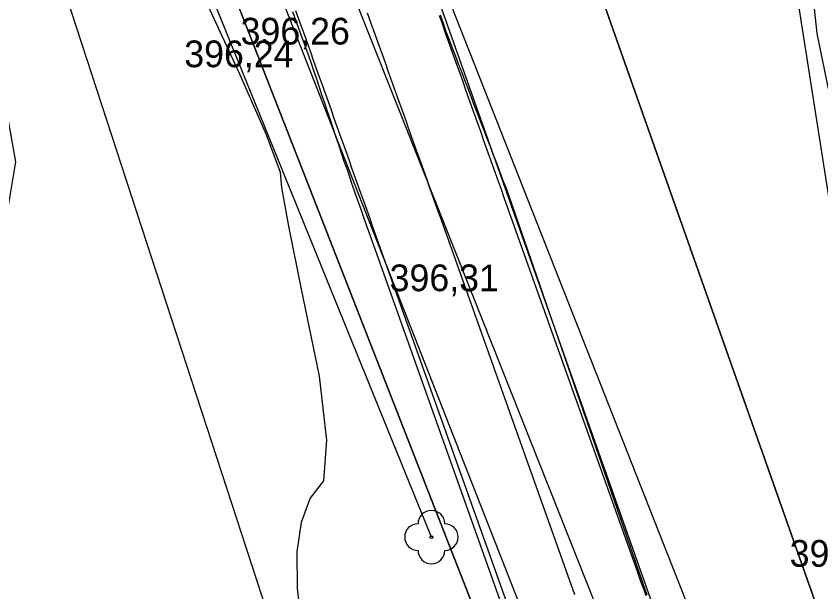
# Model space of a CAD drawing. Extents: x -574342 to -508101, y -1143544 to -1123894.
# Drawn here: x -508450.68 to -508420.54, y -1143237.66 to -1143216.1 of the extents above; entities that cross this region are included whole.
import ezdxf

# ---------------------------------------------------------------- set-up
doc = ezdxf.new("R2010")
doc.units = 0
for name, color, linetype in [('01_PARCELY_NAVRH_PC', 7, 'Continuous'), ('01_PARCELY_NAVRH_ŽP', 7, 'Continuous'), ('1000', 7, 'Continuous'), ('21', 7, 'Continuous'), ('37', 7, 'Continuous'), ('42', 7, 'Continuous'), ('54', 7, 'Continuous'), ('55', 7, 'Continuous'), ('Level 255', 7, 'Continuous'), ('VRST VEDL', 7, 'Continuous')]:
    doc.layers.add(name, color=color, linetype=linetype)

msp = doc.modelspace()

# ---------------------------------------------------------------- linework, layer by layer
at = {"layer": '01_PARCELY_NAVRH_PC'}
msp.add_lwpolyline([(-508451.57, -1143168.14), (-508437.66, -1143207.58), (-508425.52, -1143241.92), (-508422.7, -1143249.88), (-508420.08, -1143265.35), (-508416.18, -1143288.91), (-508414.34, -1143296.2), (-508410.3, -1143304.94), (-508406.96, -1143310.33), (-508402.64, -1143313.55), (-508394.5, -1143317.14), (-508397.53, -1143325.93), (-508402.47, -1143323.55), (-508407.39, -1143320.93), (-508414.82, -1143312.69), (-508418.17, -1143303.49), (-508422.28, -1143289.33), (-508426.41, -1143265.09), (-508431, -1143245.85), (-508431.86, -1143242.81), (-508432.73, -1143240.34), (-508445.99, -1143206.42), (-508454.33, -1143183.49)], dxfattribs=at)
at = {"layer": '01_PARCELY_NAVRH_ŽP'}
for points in [[(-508476.398, -1143116.058), (-508474.05, -1143124.14), (-508467.92, -1143139.18), (-508459.97, -1143152.33), (-508456.09, -1143158.71), (-508451.57, -1143168.14), (-508437.66, -1143207.58), (-508425.52, -1143241.92), (-508422.7, -1143249.88), (-508420.04, -1143252.1), (-508417.38, -1143252.95), (-508415.56, -1143252.78), (-508448.24, -1143160.16), (-508453.75, -1143145.01), (-508465.11, -1143123.03), (-508467.879, -1143116.058)], [(-508467.879, -1143116.058), (-508465.11, -1143123.03), (-508453.75, -1143145.01), (-508448.24, -1143160.16), (-508415.56, -1143252.78), (-508437, -1143116.058)]]:
    msp.add_lwpolyline(points, dxfattribs=at)
msp.add_lwpolyline([(-508455.43, -1143236.54), (-508453.14, -1143234.1), (-508452.04, -1143229.57), (-508450.69, -1143221.56), (-508452.8, -1143209.75), (-508452.72, -1143198.2), (-508454.33, -1143183.49), (-508445.99, -1143206.42), (-508432.73, -1143240.34), (-508433.72, -1143240.11), (-508438.05, -1143241.09), (-508444.11, -1143244.2), (-508446.56, -1143243.12), (-508452.58, -1143244.39)], close=True, dxfattribs=at)
at = {"layer": '1000'}
for points in [[(-508440.333, -1143215.926), (-508440.221, -1143216.235), (-508440.109, -1143216.545), (-508439.997, -1143216.855), (-508439.885, -1143217.165), (-508439.847, -1143217.271), (-508439.773, -1143217.474), (-508439.661, -1143217.784), (-508439.552, -1143218.095), (-508439.448, -1143218.407), (-508439.344, -1143218.72), (-508439.24, -1143219.033), (-508439.136, -1143219.345), (-508439.032, -1143219.658), (-508438.927, -1143219.97), (-508438.823, -1143220.282), (-508438.719, -1143220.595), (-508438.614, -1143220.907), (-508438.509, -1143221.219), (-508438.404, -1143221.532), (-508438.29, -1143221.841), (-508438.183, -1143222.152), (-508438.079, -1143222.465), (-508437.976, -1143222.778), (-508437.865, -1143223.088), (-508437.754, -1143223.398), (-508437.642, -1143223.707), (-508437.531, -1143224.017), (-508437.419, -1143224.327), (-508437.307, -1143224.637), (-508432.319, -1143238.675)], [(-508440.217, -1143215.884), (-508440.106, -1143216.195), (-508439.996, -1143216.505), (-508439.885, -1143216.815), (-508439.775, -1143217.125), (-508439.737, -1143217.232), (-508439.664, -1143217.436), (-508439.554, -1143217.746), (-508439.443, -1143218.056), (-508439.333, -1143218.366), (-508439.222, -1143218.676), (-508439.112, -1143218.987), (-508439.001, -1143219.297), (-508438.89, -1143219.607), (-508438.78, -1143219.917), (-508438.669, -1143220.228), (-508438.559, -1143220.538), (-508438.448, -1143220.848), (-508438.338, -1143221.158), (-508438.227, -1143221.469), (-508438.117, -1143221.779), (-508438.006, -1143222.089), (-508437.896, -1143222.399), (-508437.785, -1143222.71), (-508437.675, -1143223.02), (-508437.564, -1143223.33), (-508437.454, -1143223.64), (-508437.343, -1143223.951), (-508437.233, -1143224.261), (-508437.122, -1143224.571), (-508432.123, -1143238.605)], [(-508434.844, -1143216.068), (-508434.733, -1143216.378), (-508434.623, -1143216.688), (-508434.512, -1143216.999), (-508434.401, -1143217.309), (-508434.291, -1143217.619), (-508434.18, -1143217.929), (-508434.07, -1143218.239), (-508433.959, -1143218.55), (-508433.849, -1143218.86), (-508433.738, -1143219.17), (-508433.628, -1143219.48), (-508433.517, -1143219.791), (-508433.407, -1143220.101), (-508433.296, -1143220.411), (-508433.186, -1143220.721), (-508433.075, -1143221.032), (-508432.965, -1143221.342), (-508432.854, -1143221.652), (-508432.744, -1143221.962), (-508432.633, -1143222.273), (-508432.523, -1143222.583), (-508432.412, -1143222.893), (-508427.412, -1143236.927), (-508427.335, -1143237.143), (-508427.258, -1143237.36), (-508427.181, -1143237.576), (-508427.104, -1143237.793)], [(-508434.801, -1143216.053), (-508434.695, -1143216.365), (-508434.587, -1143216.676), (-508434.468, -1143216.983), (-508434.35, -1143217.29), (-508434.231, -1143217.598), (-508434.113, -1143217.905), (-508433.995, -1143218.213), (-508433.877, -1143218.52), (-508433.759, -1143218.828), (-508433.641, -1143219.136), (-508433.523, -1143219.443), (-508433.406, -1143219.751), (-508433.288, -1143220.059), (-508433.171, -1143220.366), (-508433.053, -1143220.674), (-508432.934, -1143220.981), (-508432.816, -1143221.289), (-508432.698, -1143221.596), (-508432.58, -1143221.904), (-508432.462, -1143222.211), (-508432.344, -1143222.519), (-508432.226, -1143222.827), (-508427.357, -1143236.907), (-508427.284, -1143237.125), (-508427.209, -1143237.343), (-508427.135, -1143237.56), (-508427.061, -1143237.777)]]:
    msp.add_lwpolyline(points, dxfattribs=at)
at = {"layer": '21'}
msp.add_lwpolyline([(-508437.53, -1143215.976), (-508437.42, -1143216.286), (-508437.382, -1143216.393), (-508437.309, -1143216.597), (-508437.199, -1143216.907), (-508437.088, -1143217.217), (-508436.978, -1143217.527), (-508436.867, -1143217.838), (-508436.756, -1143218.148), (-508436.646, -1143218.458), (-508436.535, -1143218.768), (-508436.425, -1143219.078), (-508436.314, -1143219.389), (-508436.204, -1143219.699), (-508436.093, -1143220.009), (-508435.983, -1143220.319), (-508435.872, -1143220.63), (-508435.762, -1143220.94), (-508435.651, -1143221.25), (-508435.541, -1143221.56), (-508435.43, -1143221.871), (-508435.32, -1143222.181), (-508435.209, -1143222.491), (-508435.099, -1143222.801), (-508434.988, -1143223.112), (-508434.878, -1143223.422), (-508434.767, -1143223.732), (-508429.767, -1143237.766)], dxfattribs=at)
at = {"layer": '37'}
for points in [[(-508473.82, -1143129.8), (-508468.34, -1143141.31), (-508458.53, -1143158.76), (-508453.13, -1143170.86), (-508439.96, -1143210.5), (-508427.56, -1143241.73), (-508421.57, -1143265.72), (-508416.35, -1143292.6), (-508412.42, -1143304.7), (-508408.82, -1143311.83)], [(-508473.82, -1143129.8), (-508468.34, -1143141.31), (-508458.53, -1143158.76), (-508453.13, -1143170.86), (-508439.96, -1143210.5), (-508427.56, -1143241.73), (-508421.57, -1143265.72), (-508416.35, -1143292.6), (-508412.42, -1143304.7), (-508408.82, -1143311.83)], [(-508408.82, -1143311.83), (-508404.37, -1143317.04), (-508398.21, -1143321.18), (-508393.66, -1143322.44), (-508393.79, -1143324.58), (-508400.56, -1143323.11), (-508406.32, -1143319.06), (-508411.41, -1143313.16), (-508415.31, -1143305.9), (-508419.33, -1143292.88), (-508424.96, -1143264.72), (-508428.49, -1143248.11), (-508430.27, -1143242.09), (-508442.28, -1143211.48), (-508455.59, -1143171.17), (-508460.82, -1143160.05), (-508470.5, -1143142.85)], [(-508408.82, -1143311.83), (-508404.37, -1143317.04), (-508398.21, -1143321.18), (-508393.66, -1143322.44), (-508393.79, -1143324.58), (-508400.56, -1143323.11), (-508406.32, -1143319.06), (-508411.41, -1143313.16), (-508415.31, -1143305.9), (-508419.33, -1143292.88), (-508424.96, -1143264.72), (-508428.49, -1143248.11), (-508430.27, -1143242.09), (-508442.28, -1143211.48), (-508455.59, -1143171.17), (-508460.82, -1143160.05), (-508470.5, -1143142.85)]]:
    msp.add_lwpolyline(points, dxfattribs=at)
at = {"layer": '42'}
msp.add_lwpolyline([(-508320.88, -1143423.96), (-508327.62, -1143411.06), (-508338.78, -1143387.2), (-508344.67, -1143370.01), (-508350.79, -1143346.58), (-508354.96, -1143336.71), (-508361.36, -1143329.02), (-508368.91, -1143322.84), (-508376.72, -1143318.72), (-508388.31, -1143315.9), (-508393.87, -1143311.09), (-508396.73, -1143306.67), (-508407.7, -1143271.35), (-508414.18, -1143248.41), (-508420.68, -1143216.75), (-508423.64, -1143189.02), (-508427.95, -1143159.6), (-508434.68, -1143117.69), (-508435.012, -1143116.058)], dxfattribs=at)
msp.add_lwpolyline([(-508320.88, -1143423.96), (-508327.62, -1143411.06), (-508338.78, -1143387.2), (-508344.67, -1143370.01), (-508350.79, -1143346.58), (-508354.96, -1143336.71), (-508361.36, -1143329.02), (-508368.91, -1143322.84), (-508376.72, -1143318.72), (-508388.31, -1143315.9), (-508393.87, -1143311.09), (-508396.73, -1143306.67), (-508407.7, -1143271.35), (-508414.18, -1143248.41), (-508420.68, -1143216.75), (-508423.64, -1143189.02), (-508427.95, -1143159.6), (-508434.68, -1143117.69), (-508435.012, -1143116.058)], dxfattribs=at)
at = {"layer": '54'}
msp.add_circle((-508435.13, -1143235.61), 0.05, dxfattribs=at)
for centre, start, end in [((-508435.13, -1143235.11), 0, 180), ((-508435.63, -1143235.61), 90, 270), ((-508434.63, -1143235.61), 270, 90), ((-508435.13, -1143236.11), 180, 0)]:
    msp.add_arc(centre, 0.5, start, end, dxfattribs=at)
at = {"layer": '55'}
msp.add_line((-508438.93, -1143245.61), (-508453.34, -1143201.44), dxfattribs=at)
msp.add_line((-508438.93, -1143245.61), (-508453.34, -1143201.44), dxfattribs=at)
for points in [[(-508435.13, -1143235.61), (-508444.83, -1143211.72), (-508456.61, -1143175.27)], [(-508435.13, -1143235.61), (-508444.83, -1143211.72), (-508456.61, -1143175.27)], [(-508410.24, -1143298.34), (-508420.04, -1143252.1), (-508438.58, -1143205.02)], [(-508410.24, -1143298.34), (-508420.04, -1143252.1), (-508438.58, -1143205.02)]]:
    msp.add_lwpolyline(points, dxfattribs=at)
at = {"layer": 'VRST VEDL'}
msp.add_lwpolyline([(-508440.011, -1143238.73), (-508440.143, -1143237.518), (-508440.157, -1143236.166), (-508439.997, -1143235.046), (-508439.665, -1143234.158), (-508439.159, -1143233.503), (-508439.046, -1143231.98), (-508439.325, -1143229.588), (-508439.996, -1143226.329), (-508440.463, -1143223.97), (-508440.727, -1143222.512), (-508440.787, -1143221.954), (-508441.311, -1143220.538), (-508442.3, -1143218.266), (-508443.753, -1143215.137)], dxfattribs=at)

# ---------------------------------------------------------------- texts
at = {"layer": 'Level 255'}
for s, p in [('396,26', (-508442.275, -1143217.16)), ('396,24', (-508444.385, -1143218.01)), ('396,31', (-508436.695, -1143226.4)), ('397,06', (-508421.715, -1143236.72))]:
    msp.add_text(s, height=1, dxfattribs=at).set_placement(p)

doc.saveas('drawing.dxf')
